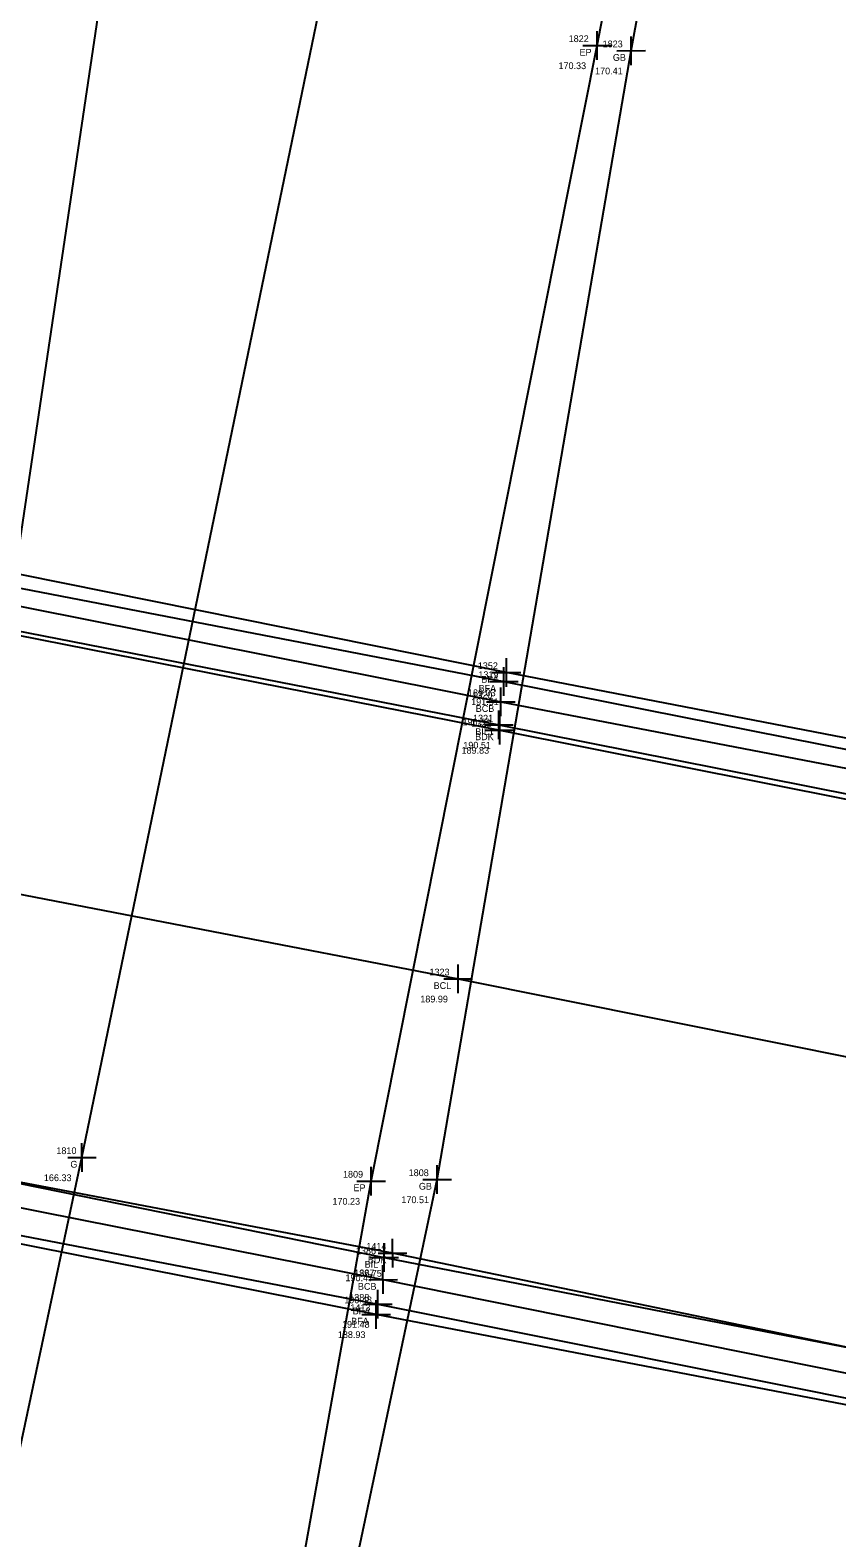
# Model space of a CAD drawing. Extents: x 1157913 to 1159198, y 600595 to 601244.
# Drawn here: x 1158606 to 1158641.8, y 600884.7 to 600951.6 of the extents above; entities that cross this region are included whole.
import ezdxf

# ---------------------------------------------------------------- set-up
doc = ezdxf.new("R2010")
doc.units = 0
for name, color, linetype in [('S_Bridge_Centerline', 7, 'Continuous'), ('S_Bridge_Curb', 7, 'Continuous'), ('S_Bridge_Deck', 7, 'Continuous'), ('S_Bridge_Fascia', 7, 'Continuous'), ('S_Bridge_Rail', 7, 'Continuous'), ('S_Field_Code', 7, 'Continuous'), ('S_Ground_Elevation', 7, 'Continuous'), ('S_Guardrail_Beam', 7, 'Continuous'), ('S_Point_Elevation', 7, 'Continuous'), ('S_Point_Name', 7, 'Continuous'), ('S_Roadway_Edge_Pavement', 7, 'Continuous'), ('S_Survey_Shot', 7, 'Continuous')]:
    doc.layers.add(name, color=color, linetype=linetype)

msp = doc.modelspace()

# ---------------------------------------------------------------- linework, layer by layer
at = {"layer": 'S_Bridge_Centerline'}
msp.add_lwpolyline([(1158481.195, 600937.121), (1158507.351, 600932.296), (1158531.006, 600927.652), (1158554.323, 600923.112), (1158577.507, 600918.68), (1158601.407, 600914.027), (1158625.013, 600909.477), (1158647.737, 600904.925), (1158672.228, 600900.301), (1158696.593, 600895.817), (1158720.484, 600890.638)], dxfattribs=at)
at = {"layer": 'S_Bridge_Curb'}
for points in [[(1158483.161, 600950.18), (1158509.184, 600944.847), (1158532.763, 600940.379), (1158556.45, 600935.563), (1158579.829, 600931.057), (1158603.376, 600926.445), (1158626.911, 600921.776), (1158650.768, 600917.187), (1158674.064, 600912.392), (1158697.671, 600908.06), (1158723.302, 600902.985)], [(1158478.174, 600924.072), (1158503.549, 600919.114), (1158527.549, 600914.557), (1158551.032, 600910.063), (1158574.638, 600905.207), (1158597.984, 600900.814), (1158621.678, 600896.121), (1158645.574, 600891.298), (1158668.721, 600886.601), (1158692.515, 600882.046), (1158718.247, 600876.909)]]:
    msp.add_lwpolyline(points, dxfattribs=at)
at = {"layer": 'S_Bridge_Deck'}
msp.add_lwpolyline([(1158483.154, 600948.642), (1158508.91, 600943.661), (1158532.625, 600939.025), (1158556.015, 600934.45), (1158579.602, 600929.788), (1158603.216, 600925.172), (1158626.871, 600920.52), (1158650.274, 600915.846), (1158673.938, 600911.396), (1158697.587, 600906.778), (1158722.887, 600901.626), (1158720.511, 600890.631), (1158717.86, 600878.361), (1158692.562, 600883.367), (1158669.405, 600887.913), (1158645.122, 600892.525), (1158622.107, 600897.299), (1158598.216, 600901.842), (1158574.819, 600906.519), (1158551.011, 600911.144), (1158527.523, 600915.567), (1158503.608, 600920.228), (1158478.738, 600925.244), (1158480.987, 600937.158)], close=True, dxfattribs=at)
at = {"layer": 'S_Bridge_Fascia'}
for points in [[(1158482.861, 600951.354), (1158482.898, 600951.287), (1158509.367, 600945.979), (1158532.925, 600941.176), (1158556.366, 600936.562), (1158579.862, 600931.952), (1158603.5, 600927.221), (1158627.041, 600922.676), (1158650.576, 600918.007), (1158674.159, 600913.359), (1158697.787, 600908.797), (1158724.39, 600903.681), (1158724.298, 600904.075), (1158697.887, 600909.28), (1158674.374, 600913.874), (1158650.514, 600918.558), (1158627.158, 600923.073), (1158603.563, 600927.819), (1158579.96, 600932.392), (1158556.434, 600937.017), (1158532.882, 600941.581), (1158509.466, 600946.154)], [(1158477.27, 600923.329), (1158503.529, 600918.158), (1158527.207, 600913.702), (1158550.741, 600909.047), (1158574.385, 600904.349), (1158597.753, 600899.594), (1158621.448, 600895.033), (1158645.16, 600890.284), (1158668.539, 600885.727), (1158692.378, 600881.174), (1158718.73, 600875.851), (1158718.692, 600875.535), (1158691.877, 600880.706), (1158668.575, 600885.39), (1158645.229, 600889.981), (1158621.38, 600894.578), (1158597.772, 600899.255), (1158574.312, 600903.82), (1158550.668, 600908.561), (1158526.887, 600913.271), (1158503.449, 600917.667), (1158477.221, 600922.938)]]:
    msp.add_lwpolyline(points, close=True, dxfattribs=at)
at = {"layer": 'S_Bridge_Rail'}
for points in [[(1158482.805, 600948.902), (1158509.002, 600943.778), (1158532.726, 600939.143), (1158579.85, 600929.84), (1158603.334, 600925.337), (1158626.819, 600920.746), (1158650.464, 600916.056), (1158674.206, 600911.454), (1158697.827, 600906.811), (1158723.142, 600901.903)], [(1158478.595, 600925.242), (1158503.898, 600920.176), (1158527.611, 600915.661), (1158551.296, 600911.071), (1158574.9, 600906.289), (1158598.35, 600901.85), (1158621.732, 600897.102), (1158645.532, 600892.49), (1158669.112, 600887.777), (1158692.742, 600883.154), (1158718.452, 600878.194)]]:
    msp.add_lwpolyline(points, dxfattribs=at)
at = {"layer": 'S_Ground_Elevation'}
for points in [[(1158542.518, 600612.987), (1158549.05, 600671.9), (1158560.427, 600727.881), (1158574.85, 600786.758), (1158585.583, 600830.044), (1158594.55, 600876.835), (1158601.243, 600899.963), (1158609.137, 600952.956), (1158616.979, 600983.866), (1158627.853, 601036.816), (1158651.057, 601155.531), (1158664.582, 601221.208)], [(1158554.911, 600670.496), (1158567.322, 600725.441), (1158582.145, 600786.225), (1158593.618, 600830.495), (1158602.851, 600875.989), (1158608.312, 600901.544), (1158618.895, 600952.688), (1158625.339, 600981.319), (1158634.969, 601035.958), (1158647.304, 601096.62), (1158640.826, 601098.491), (1158657.128, 601154.628), (1158668.824, 601220.973)]]:
    msp.add_lwpolyline(points, dxfattribs=at)
at = {"layer": 'S_Guardrail_Beam'}
msp.add_lwpolyline([(1158568.303, 600607.16), (1158579.884, 600667.953), (1158589.216, 600718.033), (1158601.774, 600785.04), (1158609.934, 600830.394), (1158618.799, 600875.575), (1158624.086, 600900.567), (1158632.701, 600950.679), (1158636.876, 600973.547)], dxfattribs=at)
at = {"layer": 'S_Roadway_Edge_Pavement'}
msp.add_lwpolyline([(1158566.514, 600606.962), (1158578.096, 600668.249), (1158588.014, 600718.546), (1158600.3, 600785.134), (1158608.291, 600830.404), (1158616.543, 600874.786), (1158621.155, 600900.499), (1158631.193, 600950.911), (1158635.412, 600972.778), (1158639.42, 600980.543), (1158643.61, 600995.24), (1158651.002, 601035.905), (1158660.818, 601092.491), (1158671.549, 601153.378), (1158684.059, 601217.652)], dxfattribs=at)
at = {"layer": 'S_Survey_Shot'}
for p, q in [((1158631.194, 600950.275), (1158631.192, 600951.547)), ((1158632.702, 600950.043), (1158632.699, 600951.315)), ((1158630.557, 600950.909), (1158631.829, 600950.912)), ((1158631.193, 600950.911), (1158631.193, 600950.911)), ((1158632.065, 600950.677), (1158633.337, 600950.68)), ((1158632.701, 600950.679), (1158632.701, 600950.679)), ((1158627.159, 600922.437), (1158627.156, 600923.709)), ((1158626.522, 600923.072), (1158627.794, 600923.075)), ((1158627.042, 600922.04), (1158627.039, 600923.312)), ((1158627.158, 600923.073), (1158627.158, 600923.073)), ((1158626.404, 600922.674), (1158627.677, 600922.677)), ((1158626.912, 600921.14), (1158626.91, 600922.412)), ((1158627.041, 600922.676), (1158627.041, 600922.676)), ((1158626.275, 600921.775), (1158627.547, 600921.777)), ((1158626.911, 600921.776), (1158626.911, 600921.776)), ((1158626.82, 600920.109), (1158626.817, 600921.382)), ((1158626.873, 600919.884), (1158626.87, 600921.156)), ((1158626.183, 600920.744), (1158627.455, 600920.747)), ((1158626.235, 600920.519), (1158627.508, 600920.521)), ((1158626.819, 600920.746), (1158626.819, 600920.746)), ((1158626.871, 600920.52), (1158626.871, 600920.52)), ((1158625.015, 600908.841), (1158625.012, 600910.113)), ((1158624.377, 600909.476), (1158625.649, 600909.478)), ((1158625.013, 600909.477), (1158625.013, 600909.477)), ((1158608.313, 600900.908), (1158608.311, 600902.18)), ((1158607.676, 600901.543), (1158608.948, 600901.545)), ((1158608.312, 600901.544), (1158608.312, 600901.544)), ((1158621.156, 600899.862), (1158621.154, 600901.135)), ((1158624.088, 600899.931), (1158624.085, 600901.203)), ((1158620.519, 600900.497), (1158621.791, 600900.5)), ((1158621.155, 600900.499), (1158621.155, 600900.499)), ((1158623.45, 600900.566), (1158624.723, 600900.568)), ((1158624.086, 600900.567), (1158624.086, 600900.567)), ((1158621.734, 600896.466), (1158621.731, 600897.738)), ((1158622.109, 600896.663), (1158622.106, 600897.935)), ((1158621.096, 600897.101), (1158622.369, 600897.103)), ((1158621.471, 600897.298), (1158622.744, 600897.301)), ((1158621.68, 600895.485), (1158621.677, 600896.758)), ((1158621.732, 600897.102), (1158621.732, 600897.102)), ((1158622.107, 600897.299), (1158622.107, 600897.299)), ((1158621.042, 600896.12), (1158622.315, 600896.123)), ((1158621.678, 600896.121), (1158621.678, 600896.121)), ((1158621.45, 600894.397), (1158621.447, 600895.669)), ((1158620.812, 600895.032), (1158622.085, 600895.035)), ((1158621.381, 600893.941), (1158621.379, 600895.214)), ((1158621.448, 600895.033), (1158621.448, 600895.033)), ((1158620.744, 600894.576), (1158622.016, 600894.579)), ((1158621.38, 600894.578), (1158621.38, 600894.578))]:
    msp.add_line(p, q, dxfattribs=at)

# ---------------------------------------------------------------- texts
at = {"layer": 'S_Field_Code'}
for s, p in [('EP', (1158630.406, 600950.461)), ('GB', (1158631.886, 600950.229)), ('BFA', (1158626.041, 600922.623)), ('BFA', (1158625.923, 600922.226)), ('BCB', (1158625.796, 600921.326)), ('BDK', (1158625.771, 600920.07)), ('BIL1', (1158625.777, 600920.296)), ('BCL', (1158623.927, 600909.027)), ('G', (1158607.797, 600901.094)), ('EP', (1158620.369, 600900.049)), ('GB', (1158623.272, 600900.117)), ('BIL', (1158620.861, 600896.652)), ('BDK', (1158621.007, 600896.849)), ('BCB', (1158620.564, 600895.671)), ('BFA', (1158620.331, 600894.583)), ('BFA', (1158620.263, 600894.128))]:
    msp.add_text(s, height=0.3, dxfattribs=at).set_placement(p)
at = {"layer": 'S_Point_Elevation'}
for s, p in [('170.33', (1158629.471, 600949.861)), ('170.41', (1158631.095, 600949.629)), ('189.03', (1158625.453, 600922.023)), ('191.51', (1158625.593, 600921.626)), ('190.53', (1158625.206, 600920.726)), ('189.83', (1158625.164, 600919.47)), ('190.51', (1158625.244, 600919.696)), ('189.99', (1158623.334, 600908.427)), ('166.33', (1158606.619, 600900.494)), ('170.23', (1158619.433, 600899.449)), ('170.51', (1158622.495, 600899.517)), ('190.47', (1158620.011, 600896.052)), ('189.75', (1158620.398, 600896.249)), ('190.48', (1158619.959, 600895.071)), ('191.48', (1158619.857, 600893.983)), ('188.93', (1158619.672, 600893.528))]:
    msp.add_text(s, height=0.3, dxfattribs=at).set_placement(p)
at = {"layer": 'S_Point_Name'}
for s, p in [('1822', (1158629.922, 600951.061)), ('1823', (1158631.43, 600950.829)), ('1352', (1158625.887, 600923.223)), ('1319', (1158625.914, 600922.826)), ('1320', (1158625.642, 600921.926)), ('1322', (1158625.601, 600920.67)), ('1321', (1158625.678, 600920.896)), ('1323', (1158623.742, 600909.627)), ('1810', (1158607.174, 600901.694)), ('1809', (1158619.901, 600900.649)), ('1808', (1158622.818, 600900.717)), ('1386', (1158620.476, 600897.252)), ('1414', (1158620.938, 600897.449)), ('1387', (1158620.405, 600896.271)), ('1388', (1158620.178, 600895.183)), ('1413', (1158620.225, 600894.728))]:
    msp.add_text(s, height=0.3, dxfattribs=at).set_placement(p)

doc.saveas('drawing.dxf')
